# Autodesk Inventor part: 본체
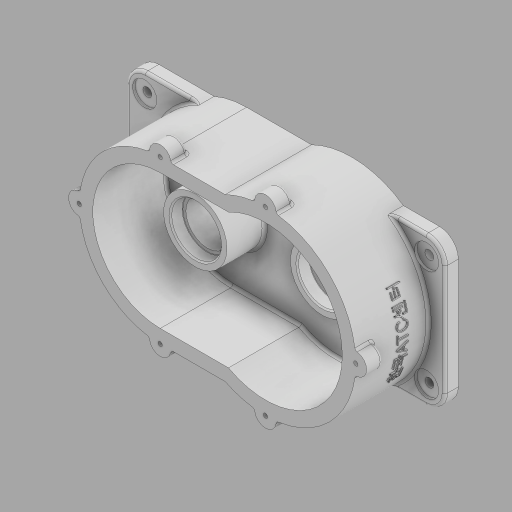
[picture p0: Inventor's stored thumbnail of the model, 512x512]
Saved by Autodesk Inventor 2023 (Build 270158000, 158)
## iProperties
Created: 2025-09
Part Number: 본체
Material: 일반
Document SubType Name: Modeling
Designer: home
Density: 1 g/cm^3
Appearance: 기본값
Author: home
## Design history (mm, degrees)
sketch "스케치1"
  geometry: L1 (118, -55)-(-118, -55); L2 (-118, -55)-(-118, 55); L3 (-118, 55)-(118, 55); L4 (118, 55)-(118, -55); L5 (118, -55)-(-118, 55); L6 (-118, -55)-(118, 55); 1 further point
  constraints: 12 end point, 2 midpoint, 2 parallel, 1 horizontal, 1 perpendicular
  dimensions: "d0" = 236 distance of L2.end L3.end; "d1" = 110 distance of L1.end L2.end
extrude "돌출1" new body sketch "스케치1" distance "d2" = 10; taper "d3" = 0 deg
sketch "스케치2"
  geometry: L1 (118, 55)-(-118, 55) reference; L2 (-118, 55)-(-118, -55) reference; L3 (-118, -55)-(118, -55) reference; L4 (118, -55)-(118, 55) reference; L5 (-39, -60)-(9.184, -60); L6 (-39, 60)-(9.184, 60); A1 r 67 centre (39, 0) between (9.184, -60) and (9.184, 60); A2 r 60 centre (-39, 0) between (-39, 60) and (-39, -60); 1 further point
  constraints: 4 end point, 4 point on circle, 2 centre point, 2 tangent, 1 horizontal, 1 parallel
  dimensions: "d10" = 134 diameter of A1; "d11" = 39 distance of point (0, 0) A2.centre; "d12" = 39 distance of A1.centre point (0, 0); "d13" = 55 distance from line of A1.centre L1; "d14" = 55 distance from line of A2.centre L1; "d15" = 60 radius of A2
extrude "돌출2" join sketch "스케치2" distance "d17" = 54; taper "d19" = 0 deg; dims "d18" = 10, "d20" = 0
sketch "스케치3"
  geometry: L1 (-39, -60)-(9.184, -60) reference; L2 (9.184, 60)-(-39, 60) reference; L3 (-39, 50)-(11.632, 50); L4 (-39, -50)-(11.632, -50); A1 r 60 centre (-39, 0) between (-39, 60) and (-39, -60) reference; A2 r 67 centre (39, 0) between (9.184, -60) and (9.184, 60) reference; A3 r 50 centre (-39, 0) between (-39, 50) and (-39, -50); A4 r 57 centre (39, 0) between (11.632, -50) and (11.632, 50); 1 further point
  constraints: 4 end point, 4 point on circle, 2 centre point, 2 coincident, 2 horizontal, 2 tangent
  dimensions: "d21" = 100 diameter of A3; "d22" = 114 diameter of A4
extrude "돌출3" cut sketch "스케치3" distance "d23" = 54; taper "d24" = 0 deg
sketch "스케치4"
  geometry: C1 r 23.5 at (-39, 0); A1 r 50 centre (-39, 0) between (-39, 50) and (-39, -50) reference; 1 further point
  constraints: 1 centre point, 1 coincident
  dimensions: "d25" = 47 diameter of C1
extrude "돌출4" join sketch "스케치4" distance "d26" = 28; taper "d27" = 0 deg
sketch "스케치5"
  geometry: C1 r 23.5 at (0, 0) reference; C2 r 18.5 at (0, 0); 1 further point
  constraints: 1 centre point, 1 coincident
  dimensions: "d28" = 37 diameter of C2
extrude "돌출5" cut sketch "스케치5" distance "d29" = 9; taper "d30" = 0 deg
sketch "스케치6"
  geometry: C1 r 18.5 at (0, 0) reference; C2 r 16 at (0, 0); 1 further point
  constraints: 1 centre point, 1 coincident
  dimensions: "d32" = 32 diameter of C2
extrude "돌출6" cut sketch "스케치6" distance "d33" = 16; taper "d34" = 0 deg
sketch "스케치7"
  geometry: C1 r 16 at (0, 0) reference; C2 r 14 at (0, 0); 1 further point
  constraints: 1 centre point, 1 coincident
  dimensions: "d35" = 28 diameter of C2
extrude "돌출7" cut sketch "스케치7" distance "d36" = 3; taper "d37" = 0 deg
chamfer "모따기1" distance "d38" = 1; stored, may be unused: second distance "d39" = 2, angle "d40" = 45 deg
fillet "모깎기1" dims "d41" = 0.3
fillet "모깎기2" dims "d42" = 2
sketch "스케치8"
  geometry: L1 (11.632, -50)-(-39, -50) reference; L2 (-39, 50)-(11.632, 50) reference; C1 r 23.5 at (-39, 0) reference; C2 r 23.5 at (39, 0); A1 r 57 centre (39, 0) between (11.632, -50) and (11.632, 50) reference; A2 r 50 centre (-39, 0) between (-39, 50) and (-39, -50) reference; 1 further point
  constraints: 1 centre point, 1 coincident
  dimensions: "d43" = 47 diameter of C2
extrude "돌출8" join sketch "스케치8" distance "d44" = 12; taper "d45" = 0 deg
sketch "스케치9"
  geometry: C1 r 23.5 at (0, 0) reference; C2 r 18.5 at (0, 0); 1 further point
  constraints: 1 centre point, 1 coincident
  dimensions: "d46" = 37 diameter of C2
extrude "돌출9" cut sketch "스케치9" distance "d47" = 9; taper "d48" = 0 deg
sketch "스케치10"
  geometry: C1 r 18.5 at (0, 0) reference; C2 r 15 at (0, 0); 1 further point
  constraints: 1 centre point, 1 coincident
  dimensions: "d49" = 30 diameter of C2
extrude "돌출10" cut sketch "스케치10" extent not by distance; stored distance "d50" = 9; taper "d51" = 0 deg
sketch "스케치11"
  geometry: L1 (-118, 55)-(-77.262, 55) reference; L2 (-118, -55)-(-118, 55) reference; L3 (-77.262, -55)-(-118, -55) reference; L4 (-9.184, -60)-(39, -60) reference; L5 (118, -55)-(62.979, -55) reference; L6 (118, 55)-(118, -55) reference; L7 (62.979, 55)-(118, 55) reference; L8 (39, 60)-(-9.184, 60) reference; C1 r 15 at (-39, 0) reference; C2 r 17.5 at (-39, 0); A1 r 67 centre (-39, 0) between (-77.262, -55) and (-9.184, -60) reference; A2 r 60 centre (39, 0) between (39, -60) and (62.979, -55) reference; A3 r 60 centre (39, 0) between (62.979, 55) and (39, 60) reference; A4 r 67 centre (-39, 0) between (-9.184, 60) and (-77.262, 55) reference; 1 further point
  constraints: 1 centre point, 1 coincident
  dimensions: "d52" = 35 diameter of C2
extrude "돌출11" cut sketch "스케치11" distance "d53" = 8.3; taper "d54" = 0 deg
chamfer "모따기2" distance "d55" = 0.8; stored, may be unused: second distance "d56" = 2, angle "d57" = 30 deg
fillet "모깎기3" dims "d58" = 0.3
chamfer "모따기3" distance "d59" = 1; stored, may be unused: second distance "d60" = 2, angle "d61" = 45 deg
fillet "모깎기4" dims "d62" = 2
sketch "스케치12"
  geometry: L1 (11.632, -50)-(-39, -50) reference; L2 (-39, 50)-(11.632, 50) reference; L3 (-39, -60)-(9.184, -60) reference; L4 (9.184, 60)-(-39, 60) reference; L5 (-29.202, 60)-(9.184, 60); L6 (9.184, -60)-(-39, -60) reference; L7 (-29.202, -60)-(9.184, -60); A1 r 57 centre (39, 0) between (11.632, -50) and (11.632, 50) reference; A2 r 50 centre (-39, 0) between (-39, 50) and (-39, -50) reference; A3 r 60 centre (-39, 0) between (-39, 60) and (-39, -60) reference; A4 r 67 centre (39, 0) between (9.184, -60) and (9.184, 60) reference; A5 r 8 centre (-99, 0) between (-99.96, 7.942) and (-99.96, -7.942); A6 r 60 centre (-39, 0) between (-39, 60) and (-62.979, 55) reference; A7 r 8 centre (-39, 60) between (-31.162, 61.6) and (-46.942, 60.96); A8 r 8 centre (-39, -60) between (-46.942, -60.96) and (-31.162, -61.6); A9 r 67 centre (39, 0) between (77.262, 55) and (9.184, 60) reference; A10 r 8 centre (39, 67) between (46.934, 68.027) and (31.066, 68.027); A11 r 67 centre (39, 0) between (77.262, -55) and (77.262, 55) reference; A12 r 8 centre (106, 0) between (107.027, -7.934) and (107.027, 7.934); A13 r 67 centre (39, 0) between (9.184, -60) and (77.262, -55) reference; A14 r 8 centre (39, -67) between (31.066, -68.027) and (46.934, -68.027); A15 r 67 centre (39, 0) between (-5.598, 50) and (-5.699, 49.91); A16 r 60 centre (-39, 0) between (-5.699, 49.91) and (-5.834, 50); A17 r 67 centre (39, 0) between (-5.699, -49.91) and (-5.598, -50); A18 r 60 centre (-39, 0) between (-5.834, -50) and (-5.699, -49.91); A19 r 67 centre (39, 0) between (9.184, -60) and (29.37, -66.304); A20 r 67 centre (39, 0) between (48.63, -66.304) and (105.304, -9.63); A21 r 67 centre (39, 0) between (105.304, 9.63) and (48.63, 66.304); A22 r 67 centre (39, 0) between (29.37, 66.304) and (9.184, 60); A23 r 60 centre (-39, 0) between (-48.607, 59.226) and (-98.226, 9.607); A24 r 60 centre (-39, 0) between (-98.226, -9.607) and (-48.607, -59.226); A25 r 2 centre (29.083, 68.284) between (29.37, 66.304) and (31.066, 68.027); A26 r 2 centre (48.917, 68.284) between (46.934, 68.027) and (48.63, 66.304); A27 r 2 centre (107.284, 9.917) between (105.304, 9.63) and (107.027, 7.934); A28 r 2 centre (107.284, -9.917) between (107.027, -7.934) and (105.304, -9.63); A29 r 2 centre (48.917, -68.284) between (48.63, -66.304) and (46.934, -68.027); A30 r 2 centre (29.083, -68.284) between (31.066, -68.027) and (29.37, -66.304); A31 r 2 centre (-29.202, -62) between (-29.202, -60) and (-31.162, -61.6); A32 r 2 centre (-48.928, -61.2) between (-46.942, -60.96) and (-48.607, -59.226); A33 r 2 centre (-100.2, -9.928) between (-98.226, -9.607) and (-99.96, -7.942); A34 r 2 centre (-100.2, 9.928) between (-99.96, 7.942) and (-98.226, 9.607); A35 r 2 centre (-48.928, 61.2) between (-48.607, 59.226) and (-46.942, 60.96); A36 r 2 centre (-29.202, 62) between (-31.162, 61.6) and (-29.202, 60); 15 further points
  constraints: 63 point on circle, 28 centre point, 28 tangent, 11 equal radius, 8 point on line, 7 end point, 3 coincident, 2 collinear
  dimensions: "d63" = 16 diameter of A5; "d64" = 16 diameter of A7; "d65" = 16 diameter of A8; "d66" = 16 diameter of A10; "d67" = 16 diameter of A12; "d68" = 16 diameter of A14; "d69" = 2 radius of A25 (derived); "d70" = 67 radius of A17; "d71" = 67 radius of A15; "d72" = 60 radius of A18; "d73" = 60 radius of A16; "d74" = 118.28358 distance from line of A26.centre L1; "d75" = 18.28358 distance from line of A29.centre L1
extrude "돌출12" join sketch "스케치12" distance "d76" = 12; taper "d77" = 0 deg
fillet "모깎기5" dims "d78" = 2
sketch "스케치13"
  geometry: L1 (11.632, -50)-(-39, -50) reference; L2 (-39, 50)-(11.632, 50) reference; L3 (-29.202, -60)-(9.184, -60) reference; L4 (9.184, 60)-(-29.202, 60) reference; L5 (-39, -60)-(-33.343, -60) reference; A1 r 57 centre (39, 0) between (11.632, -50) and (11.632, 50) reference; A2 r 50 centre (-39, 0) between (-39, 50) and (-39, -50) reference; A3 r 60 centre (-39, 0) between (-48.607, 59.226) and (-98.226, 9.607) reference; A4 r 2 centre (-100.2, 9.928) between (-99.96, 7.942) and (-98.226, 9.607) reference; A5 r 8 centre (-99, 0) between (-99.96, 7.942) and (-99.96, -7.942) reference; A6 r 2 centre (-100.2, -9.928) between (-98.226, -9.607) and (-99.96, -7.942) reference; A7 r 60 centre (-39, 0) between (-98.226, -9.607) and (-48.607, -59.226) reference; A8 r 2 centre (-48.928, -61.2) between (-46.942, -60.96) and (-48.607, -59.226) reference; A9 r 8 centre (-39, -60) between (-46.942, -60.96) and (-31.162, -61.6) reference; A10 r 2 centre (-29.202, -62) between (-29.202, -60) and (-31.162, -61.6) reference; A11 r 67 centre (39, 0) between (9.184, -60) and (29.37, -66.304) reference; A12 r 2 centre (29.083, -68.284) between (31.066, -68.027) and (29.37, -66.304) reference; A13 r 8 centre (39, -67) between (31.066, -68.027) and (46.934, -68.027) reference; A14 r 2 centre (48.917, -68.284) between (48.63, -66.304) and (46.934, -68.027) reference; A15 r 67 centre (39, 0) between (48.63, -66.304) and (105.304, -9.63) reference; A16 r 2 centre (107.284, -9.917) between (107.027, -7.934) and (105.304, -9.63) reference; A17 r 8 centre (106, 0) between (107.027, -7.934) and (107.027, 7.934) reference; A18 r 2 centre (107.284, 9.917) between (105.304, 9.63) and (107.027, 7.934) reference; A19 r 67 centre (39, 0) between (105.304, 9.63) and (48.63, 66.304) reference; A20 r 2 centre (48.917, 68.284) between (46.934, 68.027) and (48.63, 66.304) reference; A21 r 8 centre (39, 67) between (46.934, 68.027) and (31.066, 68.027) reference; A22 r 2 centre (29.083, 68.284) between (29.37, 66.304) and (31.066, 68.027) reference; A23 r 67 centre (39, 0) between (29.37, 66.304) and (9.184, 60) reference; A24 r 2 centre (-29.202, 62) between (-31.162, 61.6) and (-29.202, 60) reference; A25 r 8 centre (-39, 60) between (-31.162, 61.6) and (-46.942, 60.96) reference; A26 r 2 centre (-48.928, 61.2) between (-48.607, 59.226) and (-46.942, 60.96) reference; A27 r 8 centre (-99, 0) between (-99.96, 7.942) and (-99.96, -7.942) reference; 7 further points
  constraints: 6 coincident
hole "구멍1" sketch "스케치13" at (-99, 0), (-39, 60), (-39, -60), (39, -67), (39, 67), (106, 0) diameter "d79" = 3.242; stored, may be unused: countersink angle "d83" = 90 deg, drill point angle "d85" = 118 deg; dims "d80" = 8, "d81" = 4, "d82" = 2, "d84" = 10
fillet "모깎기6" dims "d86" = 14
sketch "스케치14"
  geometry: L1 (104.5, -41)-(-104.5, -41); L2 (-104.5, -41)-(-104.5, 41); L3 (-104.5, 41)-(104.5, 41); L4 (104.5, 41)-(104.5, -41); L5 (104.5, -41)-(-104.5, 41); L6 (-104.5, -41)-(104.5, 41); C1 r 3.3 at (-104.5, 41); C2 r 3.3 at (104.5, 41); C3 r 3.3 at (-104.5, -41); C4 r 3.3 at (104.5, -41); 1 further point
  constraints: 12 end point, 4 centre point, 3 coincident, 2 midpoint, 2 parallel, 1 horizontal, 1 perpendicular
  dimensions: "d87" = 209 distance of L2.end L3.end; "d88" = 82 distance of L1.end L2.end; "d89" = 6.6 diameter of C1; "d90" = 6.6 diameter of C2; "d91" = 6.6 diameter of C3; "d92" = 6.6 diameter of C4
extrude "돌출13" cut sketch "스케치14" extent not by distance; stored distance "d93" = 0; taper "d94" = 0 deg
sketch "스케치15"
  geometry: L1 (-118, 41)-(-118, -41) reference; L2 (-104, -55)-(-62.979, -55) reference; L3 (-62.979, 55)-(-104, 55) reference; L4 (104, 55)-(77.262, 55) reference; L5 (77.262, -55)-(104, -55) reference; L6 (118, -41)-(118, 41) reference; C1 r 3.3 at (-104.5, -41) reference; C2 r 3.3 at (-104.5, 41) reference; C3 r 3.3 at (104.5, -41) reference; C4 r 3.3 at (104.5, 41) reference; C5 r 3.3 at (-104.5, 41) reference; C6 r 9 at (-104.5, 41); C7 r 3.3 at (104.5, 41) reference; C8 r 9 at (104.5, 41); C9 r 3.3 at (-104.5, -41) reference; C10 r 9 at (-104.5, -41); C11 r 3.3 at (104.5, -41) reference; C12 r 9 at (104.5, -41); A1 r 14 centre (-104, 41) between (-104, 55) and (-118, 41) reference; A2 r 14 centre (-104, -41) between (-118, -41) and (-104, -55) reference; A3 r 60 centre (-39, 0) between (-62.979, 55) and (-62.979, -55) reference; A4 r 14 centre (104, 41) between (118, 41) and (104, 55) reference; A5 r 67 centre (39, 0) between (77.262, -55) and (77.262, 55) reference; A6 r 14 centre (104, -41) between (104, -55) and (118, -41) reference; 1 further point
  constraints: 4 centre point, 4 coincident
  dimensions: "d95" = 18 diameter of C6; "d96" = 18 diameter of C8; "d97" = 18 diameter of C10; "d98" = 18 diameter of C12
extrude "돌출14" cut sketch "스케치15" distance "d99" = 2; taper "d100" = 0 deg
fillet "모깎기7" dims "d101" = 2
node "작업 평면1"
sketch "스케치16"
  geometry: L1 (-22, 33.256)-(22, 33.256); L2 (22, 33.256)-(22, 26.744); L3 (22, 26.744)-(-22, 26.744); L4 (-22, 26.744)-(-22, 33.256); L5 (-41, 0)-(41, 0) reference; 5 further points
  constraints: 4 midpoint, 2 other
  dimensions: "d103" = 22 horizontal distance of L1.end point (0, 0); "d104" = 30 vertical distance of point (0, 0) point (22, 30); "d105" = 22 distance of point (0, 33.256) L1.start
feature "엠보싱1" sketch "스케치16" dims "d0" = 236, "d1" = 110, "d106" = 1, "d107" = 0
feature "ࠐ耀ࠒ耀ࠔ耀ࠖ耀࠘耀ࠚ耀ࠜ耀ࠞ耀" dims "d0" = 236, "d1" = 110, "d2" = 10, "d3" = 0, "d9" = 120, "d10" = 134, "d11" = 39, "d12" = 39, "d13" = 55, "d14" = 55, "d15" = 60, "d17" = 54, "d18" = 10, "d19" = 0, "d20" = 0, "d21" = 100, "d22" = 114, "d23" = 54, "d24" = 0, "d25" = 47, "d26" = 28, "d27" = 0, "d28" = 37, "d29" = 9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
node "솔리드1"
node "투영된 루프1"
node "투영된 루프2"
node "투영된 루프3"
node "투영된 루프4"
node "투영된 루프5"
node "투영된 루프6"
node "투영된 루프7"
node "투영된 루프8"
node "투영된 루프9"
node "투영된 루프10"
node "투영된 루프11"
node "투영된 루프12"
node "투영된 루프13"
feature "A9D066F2-1C7D-4E18-AEED-F7BC21143FA4" dims "d79" = 3.242, "d80" = 8, "d81" = 4, "d82" = 2, "d83" = 90 deg, "d84" = 10, "d85" = 118 deg
